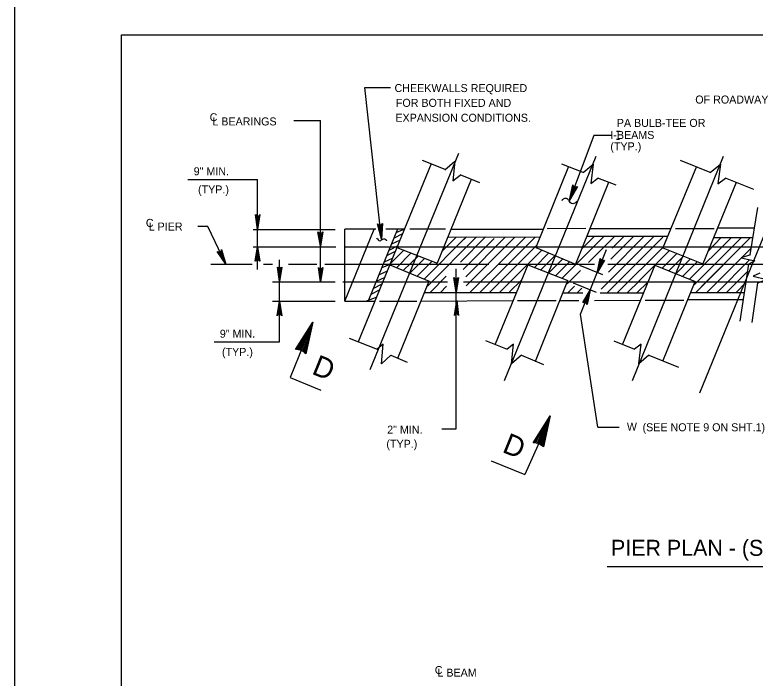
# Model space of a CAD drawing. Extents: x 639980 to 641204, y 298038 to 300414.
# Drawn here: x 639980.3 to 640257.8, y 298969.6 to 299218.3 of the extents above; entities that cross this region are included whole.
import ezdxf

# ---------------------------------------------------------------- set-up
doc = ezdxf.new("R2010")
doc.units = 0
doc.layers.add('2', color=7, linetype='Continuous')
doc.layers.add('PLT-BNDY', color=7, linetype='Continuous')

msp = doc.modelspace()

# ---------------------------------------------------------------- linework, layer by layer
at = {"layer": '2'}
for p, q in [((640020.31, 298646.78), (640020.31, 299210.78)), ((640020.31, 299210.78), (640806.31, 299210.78)), ((640237.04, 299076.6), (640284.31, 299192.29)), ((640117.78, 299134.18), (640111.51, 299190.97)), ((640111.51, 299190.97), (640121.19, 299190.97)), ((640084.94, 299178.66), (640094.84, 299178.66)), ((640094.84, 299131.68), (640094.84, 299178.66)), ((640197.31, 299173.08), (640188.26, 299148.78)), ((640203.81, 299173.08), (640197.31, 299173.08)), ((640205.89, 299174.72), (640206.93, 299174.72)), ((640205.9, 299171.72), (640206.94, 299171.72)), ((640146.68, 299166.24), (640113.38, 299085.24)), ((640198.16, 299165.16), (640163.78, 299081.1)), ((640245.86, 299165.16), (640211.66, 299081.1)), ((640136.42, 299162.46), (640109.06, 299095.68)), ((640141.64, 299160.3), (640133.18, 299163.72)), ((640187.9, 299161.38), (640175.55, 299131.05)), ((640193.3, 299159.22), (640185.38, 299162.28)), ((640235.78, 299161.38), (640223.25, 299130.87)), ((640241, 299159.22), (640229.84, 299163.72)), ((640045.22, 299156.52), (640071.26, 299156.52)), ((640071.26, 299137.08), (640071.26, 299156.52)), ((640151.36, 299156.52), (640138.61, 299125.23)), ((640154.6, 299155.26), (640147.22, 299158.32)), ((640205.72, 299154.36), (640198.88, 299157.06)), ((640257.38, 299152.74), (640246.76, 299157.06)), ((640202.84, 299155.44), (640190.49, 299124.86)), ((640250.72, 299155.44), (640238.25, 299124.87)), ((640255.94, 299128.26), (640258.82, 299146.08)), ((640052.72, 299138.88), (640048.94, 299138.88)), ((640059.38, 299124.84), (640052.72, 299138.88)), ((640069.64, 299137.8), (640100.42, 299137.8)), ((640071.26, 299131.32), (640071.26, 299137.8)), ((640104.02, 299110.98), (640104.02, 299137.98)), ((640104.02, 299110.98), (640115, 299137.98)), ((640115.64, 299137.98), (640104.02, 299137.98)), ((640123.77, 299137.98), (640112.9, 299111.25)), ((640126.34, 299137.98), (640119.36, 299137.98)), ((640125.62, 299136.18), (640122.31, 299134.4)), ((640126.34, 299137.98), (640123.17, 299136.52)), ((640141.72, 299137.98), (640128.41, 299137.98)), ((640143.8, 299137.98), (640178.36, 299137.98)), ((640194.39, 299138.15), (640179.84, 299138)), ((640195.82, 299138.16), (640226.24, 299138.16)), ((640227.9, 299138.16), (640242.44, 299138.16)), ((640257.56, 299138.34), (640243.7, 299138.34)), ((640124.72, 299133.84), (640121.48, 299132.34)), ((640133.7, 299119.24), (640148.84, 299134.38)), ((640134.98, 299116.56), (640153.34, 299135.1)), ((640140.38, 299129.52), (640145.78, 299134.92)), ((640142.72, 299135.1), (640177.1, 299134.92)), ((640147.33, 299125.59), (640156.76, 299135.1)), ((640148.43, 299122.81), (640160, 299134.38)), ((640148.66, 299134.02), (640149.56, 299135.1)), ((640149.31, 299120.09), (640164.14, 299134.92)), ((640152.44, 299119.62), (640167.74, 299134.92)), ((640154.6, 299114.22), (640175.3, 299134.92)), ((640157.84, 299121.06), (640171.7, 299134.92)), ((640185.48, 299119.54), (640201.08, 299135.14)), ((640192.76, 299130.42), (640197.66, 299135.32)), ((640194.74, 299135.28), (640225.16, 299135.28)), ((640195.34, 299125.44), (640205.18, 299135.28)), ((640200.04, 299115.38), (640219.94, 299135.28)), ((640202.3, 299114.04), (640223.18, 299134.92)), ((640202.84, 299121.84), (640216.16, 299135.28)), ((640203.74, 299126.63), (640212.38, 299135.28)), ((640204.26, 299130.76), (640208.78, 299135.28)), ((640233.16, 299119.15), (640248.92, 299134.74)), ((640234.88, 299116.92), (640252.7, 299134.74)), ((640237.76, 299116.38), (640256.12, 299134.74)), ((640240.1, 299129.52), (640245.14, 299134.74)), ((640242.26, 299134.74), (640257.02, 299134.74)), ((640069.64, 299131.32), (640100.6, 299131.32)), ((640071.26, 299122.86), (640071.26, 299131.32)), ((640094.84, 299118.18), (640094.84, 299131.32)), ((640103.87, 299131.32), (640436.3, 299131.32)), ((640123.64, 299131.5), (640120.49, 299129.93)), ((640123.54, 299131.05), (640138.61, 299125.23)), ((640158.2, 299114.22), (640175.84, 299131.86)), ((640175.55, 299131.05), (640190.49, 299124.86)), ((640206.08, 299114.04), (640223.36, 299131.14)), ((640223.25, 299130.87), (640238.25, 299124.87)), ((640239.74, 299114.22), (640256.3, 299130.78)), ((640122.92, 299129.52), (640119.67, 299127.89)), ((640126.15, 299130.04), (640121.12, 299125.02)), ((640123.36, 299123.48), (640128.87, 299128.99)), ((640125.94, 299122.42), (640131.6, 299127.94)), ((640161.98, 299114.22), (640177.86, 299130.1)), ((640175.12, 299123.57), (640180.53, 299128.99)), ((640177.54, 299122.62), (640182.83, 299128.04)), ((640192.34, 299106.04), (640202.11, 299130.25)), ((640213.82, 299118), (640225.7, 299129.88)), ((640222.91, 299123.3), (640228.41, 299128.81)), ((640079.54, 299118.18), (640079.54, 299126.46)), ((640122.02, 299127), (640118.73, 299125.59)), ((640128.35, 299121.44), (640134.04, 299126.99)), ((640131.15, 299120.29), (640136.79, 299125.93)), ((640180.41, 299121.49), (640185.75, 299126.83)), ((640182.96, 299120.44), (640188.29, 299125.77)), ((640225.47, 299122.27), (640230.98, 299127.78)), ((640228.03, 299121.23), (640233.55, 299126.75)), ((640230.59, 299120.19), (640236.13, 299125.72)), ((640243.52, 299114.22), (640255.76, 299126.46)), ((640069.29, 299124.66), (640053.8, 299124.66)), ((640076.96, 299124.66), (640073.58, 299124.66)), ((640093.58, 299124.66), (640082.94, 299124.66)), ((640158.02, 299124.66), (640096.46, 299124.66)), ((640116.79, 299120.82), (640120.04, 299122.32)), ((640120.94, 299124.66), (640117.87, 299123.48)), ((640120.87, 299124.5), (640135.63, 299118.45)), ((640145.78, 299114.22), (640145.78, 299123.04)), ((640172.6, 299124.57), (640160.36, 299094.78)), ((640197.63, 299124.66), (640161.8, 299124.66)), ((640172.6, 299124.57), (640187.65, 299118.63)), ((640187.36, 299117.46), (640192.34, 299122.43)), ((640200.74, 299120.78), (640192.07, 299124.27)), ((640202.44, 299117.78), (640207.16, 299122.5)), ((640455.92, 299124.66), (640202.59, 299124.66)), ((640220.23, 299124.39), (640208.06, 299094.78)), ((640220.23, 299124.39), (640235.35, 299118.27)), ((640235.6, 299114.22), (640245.86, 299124.48)), ((640252.16, 299103.42), (640255.4, 299124.84)), ((640118.96, 299119.8), (640115.78, 299118.33)), ((640136.06, 299114.22), (640142.04, 299120.25)), ((640149.53, 299116.71), (640153.7, 299120.88)), ((640150.82, 299114.22), (640157.84, 299121.24)), ((640247.12, 299114.22), (640255.04, 299122.14)), ((640076.84, 299118.18), (640100.42, 299118.18)), ((640079.54, 299110.98), (640079.54, 299118)), ((640103.22, 299118.18), (640142.54, 299118.18)), ((640117.88, 299117.28), (640114.7, 299115.69)), ((640123.82, 299089.56), (640135.52, 299118.18)), ((640145.78, 299109.18), (640145.78, 299118.54)), ((640148.46, 299118.18), (640437.92, 299118.18)), ((640165.76, 299114.4), (640170.08, 299118.72)), ((640175.48, 299088.48), (640187.65, 299118.63)), ((640198.39, 299114.19), (640189.72, 299117.69)), ((640209.86, 299114.04), (640214.54, 299118.72)), ((640213.46, 299114.04), (640217.6, 299118)), ((640223.18, 299088.48), (640235.35, 299118.27)), ((640237.76, 299116.38), (640240.1, 299118.72)), ((640250.72, 299114.22), (640254.5, 299118)), ((640256.66, 299102.88), (640258.82, 299117.82)), ((640117.16, 299115.12), (640113.79, 299113.43)), ((640133.9, 299114.22), (640168.28, 299114.22)), ((640139.84, 299114.22), (640142.16, 299116.54)), ((640185.74, 299114.04), (640193.23, 299114.04)), ((640187.54, 299114.04), (640190.07, 299116.57)), ((640191.14, 299114.04), (640192.85, 299115.75)), ((640199.77, 299114.04), (640215.98, 299114.04)), ((640233.62, 299114.22), (640253.78, 299114.22)), ((640111.87, 299110.98), (640116.08, 299112.6)), ((640184.66, 299111.16), (640191.68, 299111.2)), ((640197.66, 299111.24), (640214.9, 299111.34)), ((640216.56, 299111.34), (640231.1, 299111.34)), ((640232.54, 299111.52), (640253.42, 299111.52)), ((640076.84, 299110.98), (640100.42, 299110.98)), ((640079.54, 299095.68), (640079.54, 299110.98)), ((640104.02, 299110.98), (640115.36, 299110.98)), ((640117.02, 299110.98), (640131.01, 299110.98)), ((640132.64, 299110.98), (640167.02, 299111.16)), ((640145.78, 299063.02), (640145.78, 299109.18)), ((640168.68, 299111.16), (640183.22, 299111.16)), ((640198.88, 299063.64), (640192.34, 299106.04)), ((640090.05, 299098.26), (640083.57, 299082.28)), ((640055.02, 299095.68), (640079.54, 299095.68)), ((640105.64, 299097.12), (640116.08, 299092.98)), ((640156.76, 299096.22), (640164.86, 299092.98)), ((640204.82, 299096.04), (640212.56, 299092.98)), ((640121.3, 299090.64), (640127.42, 299088.12)), ((640170.26, 299090.64), (640178.54, 299087.22)), ((640217.96, 299090.64), (640229.12, 299086.14)), ((640083.57, 299082.28), (640095, 299077.55)), ((640140.38, 299063.02), (640145.78, 299063.02)), ((640198.88, 299063.64), (640206.8, 299063.64)), ((640178.01, 299060.42), (640171.53, 299045.95)), ((640158.92, 299051.14), (640171.53, 299045.95)), ((640202.29, 299011.49), (640319.04, 299011.49))]:
    msp.add_line(p, q, dxfattribs=at)
for points in [[(640141.46, 299160.12), (640145.24, 299163.36), (640144.52, 299155.98), (640147.22, 299158.14)], [(640193.3, 299159.22), (640197.08, 299162.28), (640196.18, 299155.08), (640198.88, 299157.06)], [(640241, 299159.22), (640244.78, 299162.28), (640243.88, 299154.9), (640246.76, 299157.06)], [(640190.85, 299153.73), (640190.4, 299153.67), (640188.26, 299148.78), (640190.85, 299153.73), (640191.17, 299153.91), (640188.26, 299148.78), (640189.87, 299153.86), (640189.57, 299154.18), (640188.26, 299148.78), (640189.43, 299154.56), (640189.57, 299154.18)], [(640071.98, 299143.02), (640071.62, 299142.84), (640071.26, 299137.8), (640071.98, 299143.02), (640072.16, 299143.38), (640071.26, 299137.8), (640071.08, 299142.84), (640070.72, 299143.02), (640071.26, 299137.8), (640070.54, 299143.38), (640070.72, 299143.02)], [(640117.87, 299139.76), (640117.49, 299139.51), (640117.78, 299134.18), (640117.87, 299139.76), (640118.08, 299140.07), (640117.78, 299134.18), (640116.94, 299139.44), (640116.52, 299139.59), (640117.78, 299134.18), (640116.23, 299139.86), (640116.52, 299139.59)], [(640095.56, 299136.54), (640095.2, 299136.36), (640094.84, 299131.5), (640095.56, 299136.54), (640095.74, 299136.9), (640094.84, 299131.5), (640094.66, 299136.36), (640094.3, 299136.54), (640094.84, 299131.5), (640093.94, 299136.9), (640094.3, 299136.54)], [(640070.72, 299126.1), (640071.08, 299126.28), (640071.26, 299131.32), (640070.72, 299126.1), (640070.36, 299125.92), (640071.26, 299131.32), (640071.62, 299126.28), (640071.98, 299126.1), (640071.26, 299131.32), (640072.16, 299125.92), (640071.98, 299126.1)], [(640057.76, 299129.88), (640057.4, 299129.52), (640059.38, 299124.84), (640057.76, 299129.88), (640057.76, 299130.24), (640059.38, 299124.84), (640056.86, 299129.34), (640056.5, 299129.34), (640059.38, 299124.84), (640056.14, 299129.52), (640056.5, 299129.34)], [(640256.12, 299128.26), (640252.52, 299127.18), (640257.74, 299126.1), (640255.22, 299124.66)], [(640201.14, 299126.22), (640200.74, 299126.18), (640198.63, 299121.59), (640201.14, 299126.22), (640201.37, 299126.33), (640198.63, 299121.59), (640200.24, 299126.37), (640199.96, 299126.66), (640198.63, 299121.59), (640199.69, 299126.96), (640199.96, 299126.66)], [(640080.19, 299123.51), (640079.83, 299123.33), (640079.47, 299118.29), (640080.19, 299123.51), (640080.37, 299123.69), (640079.47, 299118.29), (640079.29, 299123.33), (640078.93, 299123.51), (640079.47, 299118.29), (640078.75, 299123.69), (640078.93, 299123.51)], [(640095.56, 299123.22), (640095.2, 299123.04), (640094.84, 299118.18), (640095.56, 299123.22), (640095.74, 299123.58), (640094.84, 299118.18), (640094.66, 299123.04), (640094.3, 299123.22), (640094.84, 299118.18), (640094.12, 299123.58), (640094.3, 299123.22)], [(640146.32, 299119.44), (640145.96, 299119.26), (640145.78, 299114.22), (640146.32, 299119.44), (640146.68, 299119.8), (640145.78, 299114.22), (640145.42, 299119.26), (640145.06, 299119.44), (640145.78, 299114.22), (640144.88, 299119.8), (640145.06, 299119.44)], [(640259.54, 299121.42), (640257.02, 299120.34), (640262.24, 299119.08), (640258.64, 299117.64)], [(640193.47, 299110.49), (640193.87, 299110.52), (640196.03, 299115.09), (640193.47, 299110.49), (640193.23, 299110.38), (640196.03, 299115.09), (640194.37, 299110.33), (640194.64, 299110.03), (640196.03, 299115.09), (640194.91, 299109.73), (640194.64, 299110.03)], [(640078.82, 299105.76), (640079.18, 299105.94), (640079.54, 299110.98), (640078.82, 299105.76), (640078.64, 299105.4), (640079.54, 299110.98), (640079.72, 299105.94), (640080.08, 299105.76), (640079.54, 299110.98), (640080.44, 299105.4), (640080.08, 299105.76)], [(640145.24, 299105.94), (640145.6, 299106.12), (640145.96, 299111.16), (640145.24, 299105.94), (640145.06, 299105.58), (640145.96, 299111.16), (640146.14, 299106.12), (640146.5, 299105.94), (640145.96, 299111.16), (640146.68, 299105.58), (640146.5, 299105.94)], [(640085.51, 299092.86), (640091.99, 299103.01), (640089.4, 299091.13), (640089.18, 299091.35), (640089.62, 299092.64), (640090.05, 299094.16), (640088.97, 299091.56), (640088.75, 299091.78), (640090.48, 299095.88), (640090.7, 299097.4), (640088.54, 299092), (640088.32, 299092.21), (640091.13, 299099.12), (640091.56, 299100.85), (640088.1, 299092.21), (640087.67, 299092.43), (640091.78, 299102.36), (640091.99, 299103.01), (640091.13, 299101.71), (640087.46, 299092.43), (640087.24, 299092.64), (640090.26, 299100.2), (640089.62, 299099.12), (640087.02, 299092.64), (640086.59, 299092.64), (640088.54, 299097.61), (640087.67, 299096.1), (640086.38, 299092.86), (640085.94, 299092.86), (640087.02, 299094.8), (640085.94, 299093.51), (640085.73, 299092.86)], [(640121.3, 299090.64), (640117.7, 299087.4), (640118.42, 299094.78), (640116.08, 299092.98)], [(640170.26, 299090.64), (640166.48, 299087.4), (640167.2, 299094.78), (640164.86, 299092.98)], [(640217.96, 299090.64), (640214.18, 299087.4), (640215.08, 299094.78), (640212.56, 299092.98)], [(640174.56, 299057.83), (640181.04, 299067.98), (640178.44, 299056.32), (640178.23, 299056.54), (640178.66, 299057.62), (640179.09, 299059.13), (640178.01, 299056.75), (640177.8, 299056.75), (640179.52, 299061.07), (640179.74, 299062.58), (640177.58, 299056.97), (640177.36, 299057.18), (640180.17, 299064.1), (640180.6, 299066.04), (640177.15, 299057.4), (640176.72, 299057.4), (640180.82, 299067.55), (640181.04, 299067.98), (640180.17, 299066.69), (640176.5, 299057.62), (640176.28, 299057.62), (640179.31, 299065.39), (640178.66, 299064.1), (640176.07, 299057.62), (640175.64, 299057.83), (640177.58, 299062.58), (640176.72, 299061.07), (640175.42, 299057.83), (640175.2, 299057.83), (640176.07, 299059.99), (640174.99, 299058.48), (640174.77, 299057.83)]]:
    msp.add_lwpolyline(points, dxfattribs=at)
msp.add_arc((640174.64, 299052.36), 5.47, 45.6558, 89.9034, dxfattribs=at)
for points in [[(640191.31, 299148.56), (640190.77, 299148.02), (640189.51, 299147.48), (640188.61, 299147.84), (640188.07, 299148.56), (640187.35, 299149.28), (640186.09, 299149.28), (640185.73, 299149.1), (640185.37, 299148.56)], [(640115.9, 299134.71), (640116.2, 299134.26), (640116.8, 299133.66), (640117.55, 299133.66), (640118, 299134.11), (640118.6, 299134.26), (640119.35, 299134.11), (640119.5, 299133.81), (640119.65, 299133.51)]]:
    msp.add_spline(points, degree=3, dxfattribs=at)
at = {"layer": 'PLT-BNDY'}
msp.add_lwpolyline([(639980.31, 299225.78), (640821.31, 299225.78), (640821.31, 298631.78), (639980.31, 298631.78)], close=True, dxfattribs=at)

# ---------------------------------------------------------------- texts
at = {"layer": '2'}
for s, height, p in [('CHEEKWALLS REQUIRED', 2.9998, (640122.65, 299189.32)), ('FOR BOTH FIXED AND', 2.9998, (640123.14, 299183.78)), ('  OF ROADWAY', 2.9998, (640233.15, 299185.01)), ('C', 2.97, (640053.35, 299178.41)), ('EXPANSION CONDITIONS. ', 2.9998, (640122.96, 299178.19)), ('L BEARINGS ', 2.9998, (640054.36, 299176.81)), ('PA BULB-TEE OR', 2.9998, (640205.96, 299176.26)), (' I-BEAMS', 3, (640202.43, 299171.72)), (' (TYP.)', 3, (640202.43, 299167.47)), ('9" MIN.', 3, (640047.36, 299158.12)), ('(TYP.)', 3, (640048.99, 299151.31)), ('C', 3, (640029.43, 299138.77)), ('L PIER ', 3, (640030.48, 299137.42)), ('9" MIN.', 3, (640057.16, 299097.23)), ('(TYP.)', 3, (640057.97, 299090.42)), ('2" MIN.', 3, (640119.89, 299061.27)), ('W', 2.97, (640209.75, 299062.41)), ('(SEE NOTE 9 ON SHT.1)', 3, (640215.62, 299062.16)), ('(TYP.)', 3, (640119.59, 299055.96)), ('PIER PLAN - (SKEWED) ', 6, (640203.79, 299015.47)), ('C', 2.97, (640137.75, 298971.17)), ('L BEAM', 3, (640138.73, 298970.16))]:
    msp.add_text(s, height=height, dxfattribs=at).set_placement(p)
for p in [(640091.26, 299083.8), (640162.65, 299054.49)]:
    msp.add_text('D', height=7.78, rotation=338, dxfattribs=at).set_placement(p)

doc.saveas('drawing.dxf')
